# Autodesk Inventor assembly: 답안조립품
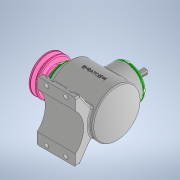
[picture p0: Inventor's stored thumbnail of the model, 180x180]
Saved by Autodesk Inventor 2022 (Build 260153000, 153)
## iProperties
Created: 2023-04
Part Number: 답안조립품
Document SubType Name: Assembly
Designer: ADMIN_PC
Author: ADMIN_PC
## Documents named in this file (17)
- C:\Users\ADMIN_PC\Desktop\730411V1011\답안조립품.iam
- C:\Users\ADMIN_PC\Desktop\730411V1011\본체.ipt
- C:\Users\ADMIN_PC\Desktop\730411V1011\커버.ipt
- C:\Users\ADMIN_PC\Desktop\730411V1011\베어링 6203.ipt
- C:\Users\ADMIN_PC\Desktop\730411V1011\오일실 17 x 32 x 8.ipt
- C:\Users\ADMIN_PC\Desktop\730411V1011\서브 축.ipt
- 서브 축.ipt
- C:\Users\ADMIN_PC\Desktop\730411V1011\메인 축.ipt
- 메인 축.ipt
- C:\Users\ADMIN_PC\Desktop\730411V1011\키 5 x 5 x 14.ipt
- C:\Users\ADMIN_PC\Desktop\730411V1011\키 4 x 4 x 14.ipt
- C:\Users\ADMIN_PC\Desktop\730411V1011\메인 베벨기어.ipt
- C:\Users\ADMIN_PC\Desktop\730411V1011\서브 베벨기어.ipt
- C:\Users\ADMIN_PC\Desktop\730411V1011\육각볼트 M4 x 8.ipt
- C:\Users\ADMIN_PC\Desktop\730411V1011\V-벨트풀리.ipt
- C:\Users\ADMIN_PC\Desktop\730411V1011\볼트 M4 x 10.ipt
- C:\Users\ADMIN_PC\Desktop\730411V1011\와셔 4 x 16.ipt
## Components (1 placed, 1 different names)
1. V-벨트풀리:1 — 플러쉬:1
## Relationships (1: Flush 1)
- 플러쉬:1 [Flush]: V-벨트풀리:1
